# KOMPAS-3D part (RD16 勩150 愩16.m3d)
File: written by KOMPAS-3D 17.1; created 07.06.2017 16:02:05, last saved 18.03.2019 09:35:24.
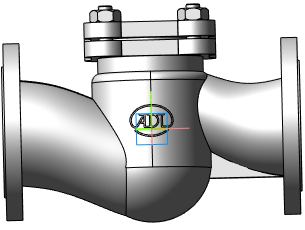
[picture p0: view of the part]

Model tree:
1. Операция без истории:3  (labels: Сталь 20  ГОСТ 1050-88)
